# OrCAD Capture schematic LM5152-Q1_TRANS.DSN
size Custom; title: LM5152-Q1 2.2-MHz Wide VIN Low-IQ Synchronous; rev: 1.0; note: Datasheet: NA     EVM: NA; note: Synchronous Step Down Converter
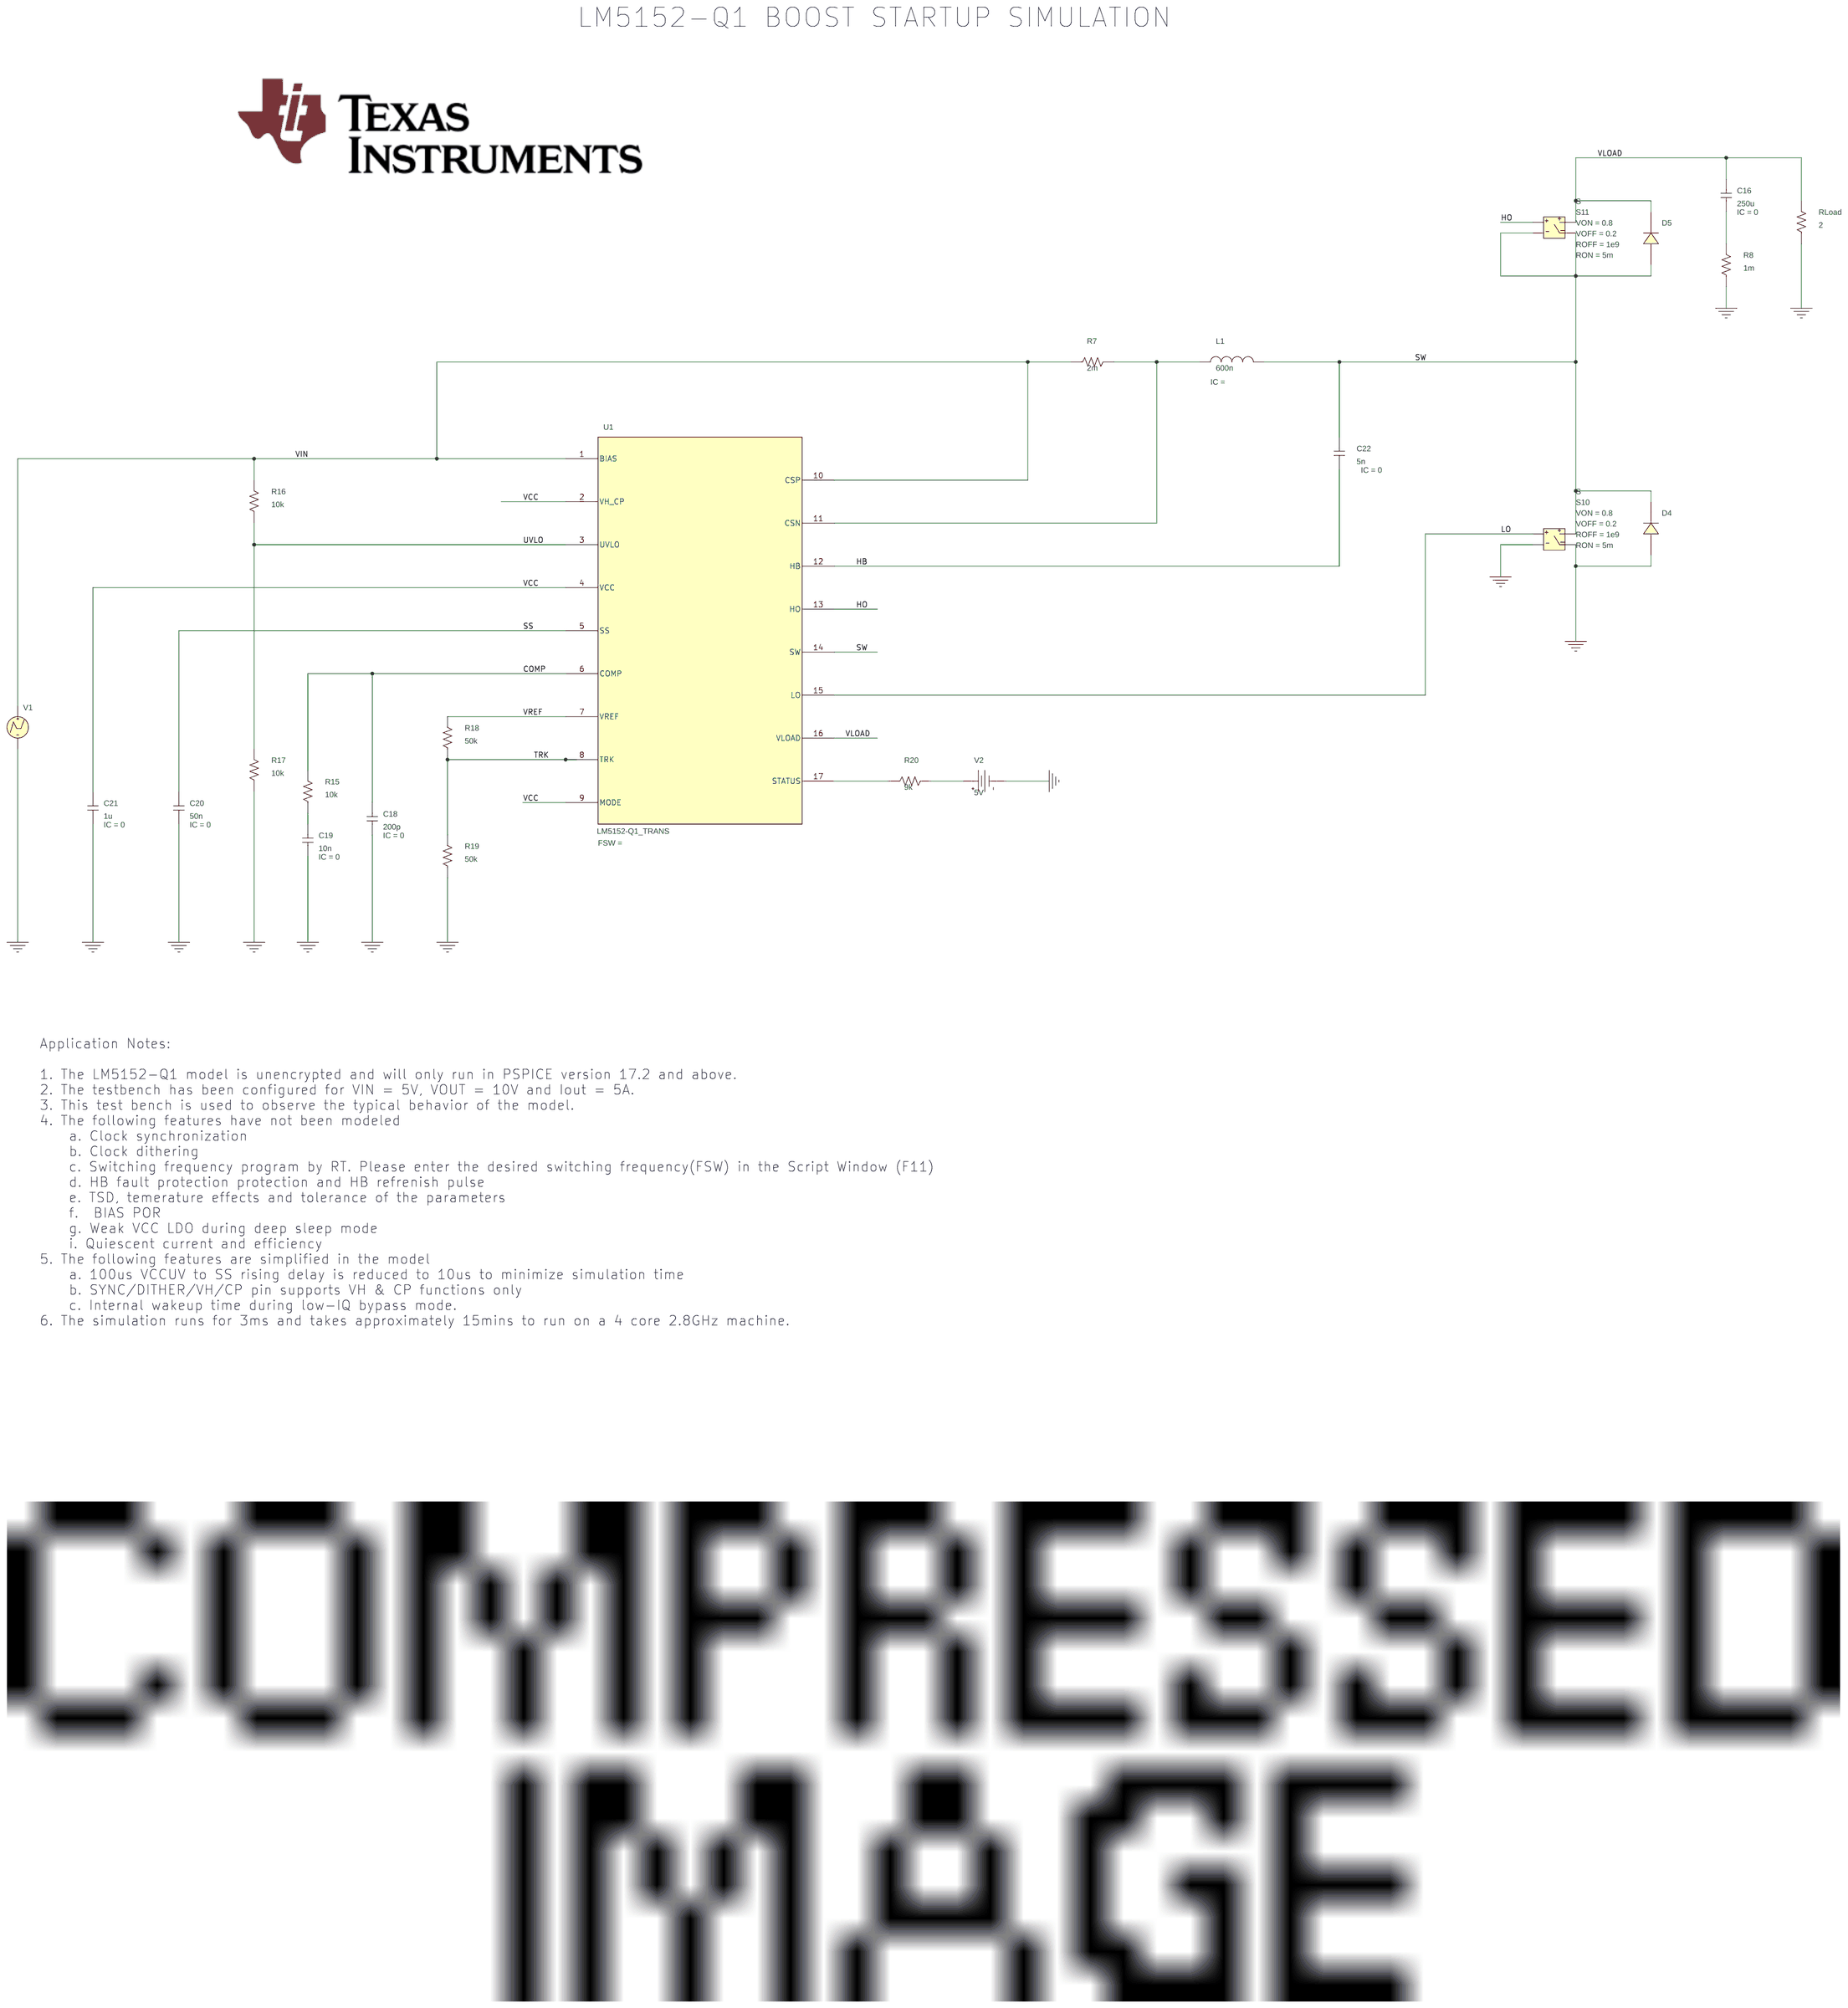
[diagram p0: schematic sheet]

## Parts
C16  250u  [RAD/CK05]
C18  200p  [RAD/CK05]
C19  10n  [RAD/CK05]
C20  50n  [RAD/CK05]
C21  1u  [RAD/CK05]
C22  5n  [RAD/CK05]
D4  D_D1
D5  D_D1
L1  600n  [DISC/.350x.175/LS.200x.100/.034]
R7  2m  [AX/RC05]
R8  1m  [AX/RC05]
R15  10k  [AX/RC05]
R16  10k  [AX/RC05]
R17  10k  [AX/RC05]
R18  50k  [AX/RC05]
R19  50k  [AX/RC05]
R20  9k  [AX/RC05]
RLoad  2  [AX/RC05]
S10  S
S11  S
U1  LM5152-Q1_TRANS
V1  VPWL
V2  VDC

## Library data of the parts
C16 C18-C22 = C: IC: 0
D4 D5 = D_D1
L1 = L
R7 R8 R15-R20 RLoad = R
S10 S11 = S: ROFF: 1e9; RON: 5m; VOFF: 0.2; VON: 0.8
U1 = LM5152-Q1_TRANS
V1 = VPWL: T1: 0m; T2: 1m; T3: 2m; V1: 0; V2: 5; V3: 5
V2 = VDC: DC: 5V

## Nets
VCC: C21.2 U1.2(VH_CP) U1.4(VCC) U1.9(MODE)
VIN: R7.1 R16.2 U1.1(BIAS) U1.10(CSP) V1.1(+)
0: C18.1 C19.1 C20.1 C21.1 D4.2(A) R8.1 R17.1 R19.1 RLoad.1 S10.1(2) S10.3(4) V1.2(-) V2.1(-)
COMP: C18.2 R15.2 U1.6(COMP)
HB: C22.1 U1.12(HB)
HO: S11.0(1) U1.13(HO)
LO: S10.0(1) U1.15(LO)
SS: C20.2 U1.5(SS)
SW: C22.2 D4.1(C) D5.2(A) L1.2 S10.2(3) S11.1(2) S11.3(4) U1.14(SW)
TRK: R18.1 R19.2 U1.8(TRK)
UVLO: R16.1 R17.2 U1.3(UVLO)
VLOAD: C16.2 D5.1(C) RLoad.2 S11.2(3) U1.16(VLOAD)
VREF: R18.2 U1.7(VREF)
N16776369: C16.1 R8.2
N16776571: L1.1 R7.2 U1.11(CSN)
N16777218: R20.1 U1.17(STATUS)
N16777221: R20.2 V2.0(+)
N16777252: C19.2 R15.1

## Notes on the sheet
- LM5152-Q1 BOOST STARTUP SIMULATION
- Application Notes:
  1. The LM5152-Q1 model is unencrypted and will only run in PSPICE version 17.2 and above.
  2. The testbench has been configured for VIN = 5V, VOUT = 10V and Iout = 5A.
  3. This test bench is used to observe the typical behavior of the model.
  4. The following features have not been modeled
      a. Clock synchronization
      b. Clock dithering
      c. Switching frequency program by RT. Please enter the desired switching frequency(FSW) in the Script Window (F11)
      d. HB fault protection protection and HB refrenish pulse
      e. TSD, temerature effects and tolerance of the parameters
      f.  BIAS POR
      g. Weak VCC LDO during deep sleep mode
      i. Quiescent current and efficiency
  5. The following features are simplified in the model
      a. 100us VCCUV to SS rising delay is reduced to 10us to minimize simulation time
      b. SYNC/DITHER/VH/CP pin supports VH & CP functions only
      c. Internal wakeup time during low-IQ bypass mode.
  6. The simulation runs for 3ms and takes approximately 15mins to run on a 4 core 2.8GHz machine.
